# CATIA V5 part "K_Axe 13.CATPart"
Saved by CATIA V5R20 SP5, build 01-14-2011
Part number: Axe 13
Bounding box of the stored display mesh (mm): x -15.996 to 15.996, y 1 to 119, z -15.999 to 15.999
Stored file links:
  G:\Khaled_CFAO_2011\SIL\SIL_GR1\gperrin\Khaled\CAD_CATIA\Khaled\K_Axe 13.CATPart
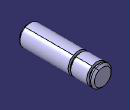
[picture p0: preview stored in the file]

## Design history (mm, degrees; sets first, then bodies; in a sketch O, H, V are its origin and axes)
Body1 (main body)
  Sketch1 on yz-plane, origin (0, 0, 0), H (0, 1, 0), V (0, 0, 1)
    axis line L1 (-43, 0) -> (96, 0)
    point P1 (-43, 0)
    point P3 (1, 0)
    line L2 (1, 11.4065) -> (1, 0)
    point P4 (1, 16)
    line L3 (114, 16) -> (114, 12)
    line L4 (114, 12) -> (110, 12)
    line L5 (110, 12) -> (110, 16)
    point P9 (81, 16)
    line L6 (85, 16) -> (85, 12)
    line L7 (85, 12) -> (81, 12)
    line L8 (81, 12) -> (81, 16)
    point P11 (85, 12)
    line L9 (85, 16) -> (110, 16)
    line L10 (81, 16) -> (5.5935, 16)
    line L11 (5.5935, 16) -> (1, 11.4065)
    line L12 (114, 16) -> (115.9856, 16)
    line L13 (119, 12.9856) -> (119, 0)
    point P15 (119, 0)
    line L14 (115.9856, 16) -> (119, 12.9856)
    length L4 = 4
    length L7 = 4
    length L9 = 25
    distance P9 P4 = 80
    distance P4 P3 = 16
    angle L10 L11 = 45
    length L11 = 6.4963
    angle L12 L14 = 45
    length L14 = 4.263
    coincidence: P1 H, P3 L1, P11 L4, L10 P4, L2 P4, P15 L1
    horizontal: L1 H, L4 H, L7 H, L9 H, L10 H, L12 H
    vertical: L2 V, L3 V, L5 V, L6 V, L8 V, L13 V
  Shaft1: profile Sketch1, axis Sketch1.L1, angle 360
